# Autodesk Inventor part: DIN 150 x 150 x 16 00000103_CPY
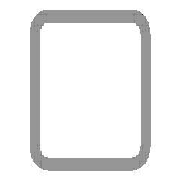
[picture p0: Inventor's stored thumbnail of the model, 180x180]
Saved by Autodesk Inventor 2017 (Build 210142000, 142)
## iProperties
Created: 2017-11
Part Number: DIN 150 x 150 x 16 00000103_CPY
Material: Steel, Mild
Description: Cold formed welded structural hollow sections of non-alloy and fine grain structural steel
Document SubType Name: Modeling
Standard: DIN
Designer: iusti
Standard Revision: 2006-07
Standards Organization: DIN
Language: en-US
Size Designation: 150 x 150 x 16
Categories: <MemberInstance><Categories><Category DisplayName="Structural Shapes" InternalName="089c4875-fa83-4c05-b084-43b9cc11f5ed" Mnemonic="GRDR"><CategoryParameter Dis
Stock Number: 150 x 150 x 16
Mass: 90369.3 g
Surface Area: 14539.6 cm^2
Volume: 11512 cm^3
Density: 7.85 g/cm^3
Appearance: Semi-Polished
IsCustomPart: 1
G_W: 150.000 mm
G_H: 150.000 mm
G_L: 1539.608 mm
+B4BE7288-8744-4333-8402-F61C489DE7FB+CUTDETAIL2: Cut
_CCFamilyMember: 76
_CCFamilyDisplayName: DIN EN 10219-2 (Square Hollow Section - Cold Formed) - Cold formed welded structural hollow sections of non-alloy and fine grain structural steel
_FrameMemberDoc: Frame Member File
_Version: 15.0.0
_GetPNFromCC: 1
Author: iusti
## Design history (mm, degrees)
node "Start plane"
node "End plane"
sketch "Sketch"
  geometry: L1 (-75, -27)-(-75, 27); L2 (-27, 75)-(27, 75); L3 (75, 27)-(75, -27); L4 (27, -75)-(-27, -75); L5 (-27, 59)-(27, 59); L6 (59, 27)-(59, -27); L7 (27, -59)-(-27, -59); L8 (-59, -27)-(-59, 27); L9 (0, 118.918)-(0, -118.918) reference; L10 (-118.918, 0)-(118.918, 0) reference; A1 r 48 centre (-27, -27) between (-75, -27) and (-27, -75); A2 r 48 centre (-27, 27) between (-27, 75) and (-75, 27); A3 r 48 centre (27, 27) between (75, 27) and (27, 75); A4 r 48 centre (27, -27) between (27, -75) and (75, -27); A5 r 32 centre (-27, 27) between (-27, 59) and (-59, 27); A6 r 32 centre (27, 27) between (59, 27) and (27, 59); A7 r 32 centre (27, -27) between (27, -59) and (59, -27); A8 r 32 centre (-27, -27) between (-59, -27) and (-27, -59)
  constraints: 16 end point, 16 point on circle, 8 centre point, 8 tangent, 4 parallel, 3 equal radius, 2 perpendicular, 7 other
  dimensions: "d7" = 48 radius of A1 (= G_IR); "d10" = 150 distance between parallel lines of L2 L4 (= G_H); "d11" = 150 distance between parallel lines of L1 L3 (= G_W); "d12" = 16 distance between parallel lines of L3 L6 (= G_T); "d15" = 75 distance between parallel lines of L2 L10 (= 0.5 x d10); "d16" = 75 distance between parallel lines of L9 L3 (= 0.5 x d11)
extrude "Body" new body sketch "Sketch" stored distance "d3" = 1539.60835 (= G_L); taper "d4" = 0 deg
node "Driven Length"
  sketch "Sketch3"
    geometry: L1 (0, 0)-(10, 0) reference
    constraints: 2 end point, 1 horizontal
  workplane "Work Plane3"
  sketch "Sketch4"
    geometry: L1 (-2, 75)-(12, 75) reference; L2 (-2, 1614.608)-(12, 1614.608) reference
    dimensions: "d18" = 1539.60835 distance between parallel lines of L1 L2 (derived)
workplane "Work Plane5"
split "Split2"
body "Solid1"
other parameters: "G_W" = 150 [user parameter; used in 1 equation term], "G_H" = 150 [user parameter; used in 1 equation term], "G_T" = 16 [user parameter; used in 1 equation term], "G_IR" = 48 [user parameter; used in 1 equation term], "G_L" = 1539.60835 (= d18) [user parameter; used in 1 equation term], "G_OFFSET_START" = -75 [user parameter; used in 1 equation term], "G_OFFSET_END" = 0 [user parameter; used in 1 equation term], "d13" = 75 (= -G_OFFSET_START), "d14" = 1614.60835 (= G_OFFSET_END + B_L), "B_L" = 1614.60835 [user parameter; used in 1 equation term], "d17" = 90 deg
